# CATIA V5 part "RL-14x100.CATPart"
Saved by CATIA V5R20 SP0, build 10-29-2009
Part number: _RL-14x100
Definition: NONE
Nomenclature: _RL-14x100
Source: Unknown
Description: PART-_RL-14x100-DESC
Bounding box of the stored display mesh (mm): x -100 to 12.5, y -8 to 8, z -8 to 8
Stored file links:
  C:\Users\Utente\Desktop\IO LAVORO\3D X SITO CF\X SITO\PLASTICA\RL\RL-14x100.CATPart
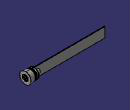
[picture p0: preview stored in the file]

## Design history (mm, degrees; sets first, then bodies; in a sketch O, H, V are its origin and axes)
Body1 "_RL-14x100" (main body)
  Solid1: solid without history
